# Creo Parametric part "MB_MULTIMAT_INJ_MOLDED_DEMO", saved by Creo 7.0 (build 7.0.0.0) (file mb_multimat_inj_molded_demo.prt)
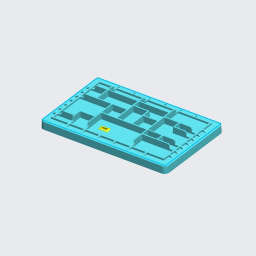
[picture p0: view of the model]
Units: millimeter Kilogram Sec (mmKs); MM, KILOGRAM, SECS
Materials in the file: PA66-GF, SILICONE_RUBBER

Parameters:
  GRANTA_DATALINK_VERSION = "5"
  GRANTA_DATABASE_KEY = "Granta_Typical_Materials"
  GRANTA_IDENTITY_GUID = "1dec458e-fa0e-4d28-aa1b-3d14c5a24b26"
  GRANTA_VERSION_GUID = "d12aeece-3595-47ca-ae7c-e67cefe245a1"
  GRANTA_MODEL_REFERENCE = "00000000-0000-0000-0000-000000000000"

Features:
  1. datum plane "RIGHT"
  2. datum plane "TOP"
  3. datum plane "FRONT"
  4. coordinate system
  5. curve
  6. protrusion
  7. protrusion
  8. datum plane "DTM1"
  9. datum plane "DTM2"
  10. curve
  11. protrusion
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
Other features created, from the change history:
  group "CUTOUT_PORT_W_OVERM_TYPE_A"
  datum plane "YZ"
  datum plane "TOP_PLUS_HEIGHT"
  datum plane "BOTTOM_PLUS_HEIGHT"
  sketch "Sketch 5" (2 times)
  extruded cut "Extrude 5"
  extrusion "Extrude 6"
  extrusion "Extrude 7"
  round "Round 11"
  round "Round 12"
  protrusion "Sweep 5"
  feature "Body Subtract 2"
  extrusion "Extrude 8"
  feature "Body Subtract 3"
  planar section "XSEC0001" (3 times)
  planar section "XSEC0002"
  datum plane "DTM3"

Other named items: HOUSING_BASE, OVERMOLD_1, CS0, HOUSING, OVERMOLD1, WITH_OVERMOLD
